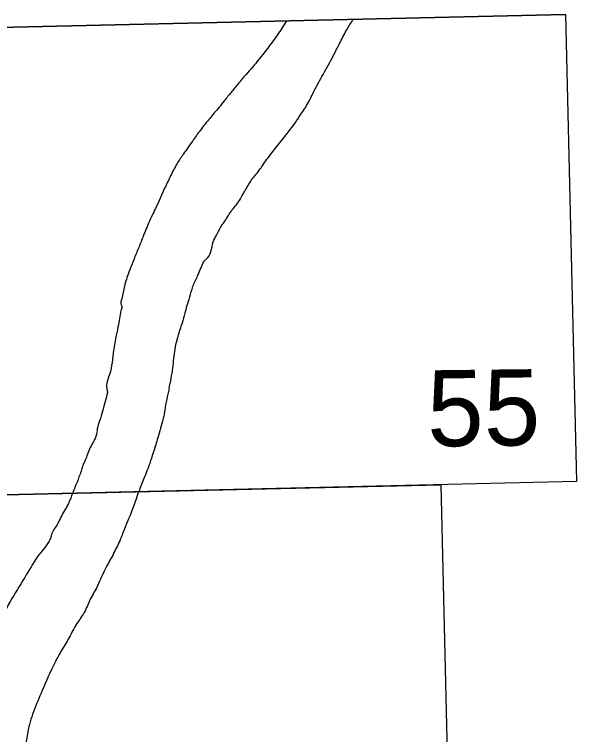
# Model space of a CAD drawing. Extents: x 3678539 to 3716648, y 451386 to 477139.
# Drawn here: x 3705022 to 3705886, y 455026 to 456133 of the extents above; entities that cross this region are included whole.
import ezdxf

# ---------------------------------------------------------------- set-up
doc = ezdxf.new("R2010")
doc.units = 0
doc.layers.add('V-ANNO-NPLT', color=7, linetype='Continuous')

msp = doc.modelspace()

# ---------------------------------------------------------------- linework, layer by layer
at = {"layer": 'V-ANNO-NPLT'}
for points in [[(3705869.1, 456132.6), (3704617.3, 456103.7)], [(3704633.6, 455385.7), (3704617.3, 456103.7), (3705869.1, 456132.6), (3705886, 455414.7)], [(3704441.1, 454663), (3704424.9, 455381), (3705677.3, 455409.8), (3705694.1, 454691.8)], [(3705886, 455414.7), (3704633.6, 455385.7)]]:
    msp.add_lwpolyline(points, dxfattribs=at)
for points in [[(3705440.2, 456122.7), (3705427.4, 456103.2), (3705405.6, 456073.7), (3705387.5, 456051.3), (3705377.8, 456040.3), (3705365.3, 456025.5), (3705354.9, 456012.6)], [(3705482, 456014.1), (3705496.3, 456040.5), (3705512.5, 456070), (3705521.6, 456088.1), (3705532.3, 456108.5), (3705543.1, 456125.5)], [(3705354.9, 456012.6), (3705344.2, 455999.8), (3705336.4, 455989.9), (3705329, 455981.2), (3705315, 455964.1), (3705307.2, 455954.3), (3705295.8, 455938.4), (3705288.4, 455927.8), (3705281.8, 455918.3)], [(3705404.5, 455902.5), (3705419.3, 455922.2), (3705435.6, 455942.3), (3705455.5, 455969.1), (3705459.2, 455974.6), (3705471, 455992.6), (3705482.1, 456014.2)], [(3705281.8, 455918.3), (3705271.8, 455903.5), (3705261.9, 455884.6), (3705252.7, 455865.4), (3705239.9, 455837.1), (3705229.3, 455814.8), (3705219.8, 455791.8)], [(3705332.3, 455793.5), (3705340.7, 455808.6), (3705345.2, 455815), (3705356.2, 455831.7), (3705369.1, 455849.1), (3705371.3, 455853.3), (3705374.3, 455858.2), (3705375.8, 455860.8), (3705386.4, 455878.2), (3705399.7, 455895.2), (3705404.7, 455902.7)], [(3705219.8, 455791.8), (3705212.9, 455774.5), (3705205.6, 455756.8), (3705199.8, 455741.7), (3705192.2, 455719.8), (3705190.4, 455712.7), (3705186.1, 455693.1), (3705185.4, 455688.2), (3705185.8, 455686.7), (3705186.6, 455684.9), (3705185.5, 455677.7)], [(3705286.3, 455682.6), (3705291.4, 455698.4), (3705296.1, 455714.3), (3705303.4, 455730.9), (3705312.9, 455752.4), (3705314, 455754.3), (3705315.1, 455755.4), (3705316.6, 455756.5), (3705327.5, 455782.9), (3705332.3, 455793.5)], [(3705185.5, 455677.7), (3705180.9, 455652.5), (3705174.2, 455616.4), (3705167.9, 455579.2), (3705163.7, 455557.7), (3705164.4, 455554.7), (3705164.8, 455551.7)], [(3705259.6, 455557.3), (3705265.3, 455589.3), (3705268.7, 455617.9), (3705276.2, 455647.2), (3705285.3, 455677.7), (3705286.3, 455682.6)], [(3705164.8, 455551.7), (3705161.3, 455537.8), (3705152.6, 455508.1), (3705150.4, 455501.6), (3705145.1, 455479.1), (3705142.1, 455474.2), (3705133.3, 455454.2), (3705129.3, 455445.1), (3705127.1, 455439.4)], [(3705259.6, 455557.3), (3705252.9, 455524.2), (3705252.2, 455519.3), (3705250.4, 455511.4), (3705242.1, 455481.7), (3705238.9, 455471.1), (3705232, 455449.3), (3705230.2, 455443.6)], [(3705230.2, 455443.6), (3705220.7, 455419.1), (3705212.8, 455399.1)], [(3705127.1, 455439.4), (3705121, 455421.7), (3705114.8, 455405.9), (3705111.1, 455396.8)], [(3705111.1, 455396.8), (3705104.9, 455381), (3705101.6, 455375), (3705090.6, 455355), (3705087.3, 455348.2), (3705078.5, 455333), (3705077.4, 455327.8), (3705075.2, 455323.2), (3705057.1, 455299.4)], [(3705173.3, 455301.9), (3705183.6, 455322.6), (3705186.2, 455329), (3705189.1, 455336.6), (3705202.9, 455370.5), (3705212.8, 455399.1)], [(3705057.1, 455299.4), (3705037.5, 455267.4), (3705015.3, 455230.4), (3705004.5, 455209.2), (3704997.2, 455188.9), (3704977, 455152)], [(3705173.3, 455301.9), (3705155.6, 455268.2), (3705149.7, 455254.6), (3705138.4, 455233.8), (3705129.1, 455213.6), (3705117.7, 455196.4), (3705105.9, 455175.1), (3705093.1, 455153.3)], [(3705093.1, 455153.3), (3705083.7, 455136.1), (3705064.6, 455093.6), (3705050.9, 455060.8), (3705042.2, 455029.5), (3705038.5, 455006.8)]]:
    msp.add_spline(points, degree=3, dxfattribs=at)

# ---------------------------------------------------------------- texts
msp.add_text('55', height=117, rotation=0.6583, dxfattribs=at).set_placement((3705656.7, 455468.6))

doc.saveas('drawing.dxf')
